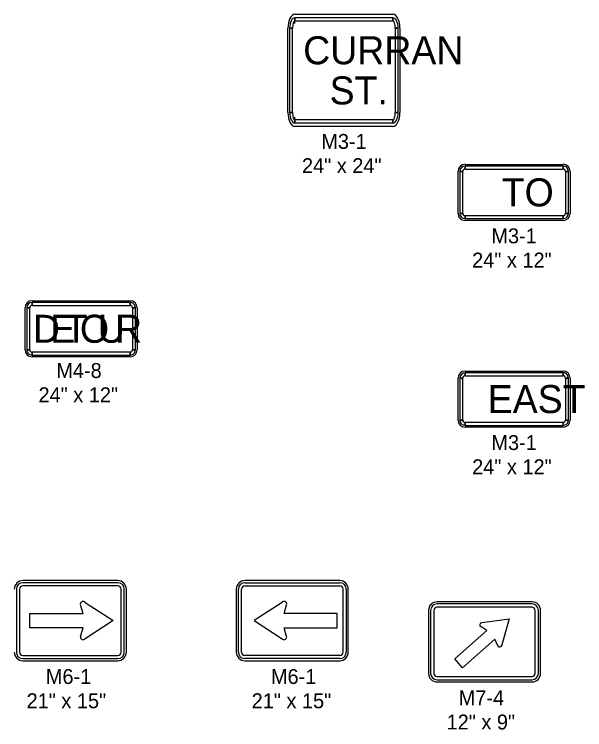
# Model space of a CAD drawing. Extents: x 10133 to 81668, y 6132 to 11018.
# Drawn here: x 10961.7 to 11267.8, y 6734.5 to 7118.2 of the extents above; entities that cross this region are included whole.
import ezdxf

# ---------------------------------------------------------------- set-up
doc = ezdxf.new("R2010")
doc.units = 0
for name, color, linetype in [('dsnTextFinalPlan', 7, 'Continuous'), ('Level 10', 7, 'Continuous'), ('Level 5', 7, 'Continuous')]:
    doc.layers.add(name, color=color, linetype=linetype)

msp = doc.modelspace()

# ---------------------------------------------------------------- linework, layer by layer
at = {"layer": 'dsnTextFinalPlan'}
for p, q in [((11239.58, 6803.08), (11188.62, 6803.08)), ((11184.03, 6798.5), (11184.03, 6764.72)), ((11244.16, 6764.72), (11244.16, 6798.5)), ((11188.62, 6760.13), (11239.58, 6760.13))]:
    msp.add_line(p, q, dxfattribs=at)
for points in [[(11212.88, 6791.95), (11227.25, 6794.02), (11223.39, 6780.04)], [(11221.17, 6779.52), (11219.55, 6783.04), (11202.22, 6767.75), (11198.07, 6772.46), (11215.39, 6787.75), (11212.1, 6789.78)]]:
    msp.add_lwpolyline(points, dxfattribs=at)
for centre, radius, start, end in [((11188.62, 6798.5), 4.58, 90, 180), ((11239.58, 6798.5), 4.58, 360, 90), ((11212.72, 6790.75), 1.16, 98.0346, 237.3927), ((11196.35, 6906.73), 115.96, 278.0346, 278.1951), ((11222.2, 6780.01), 1.14, 205.4546, 344.7341), ((11335.17, 6749.18), 115.96, 164.5667, 164.7341), ((11188.62, 6764.72), 4.58, 180, 270), ((11239.58, 6764.72), 4.58, 270, 0)]:
    msp.add_arc(centre, radius, start, end, dxfattribs=at)
at = {"layer": 'Level 10'}
for p, q in [((11112.34, 7118.21), (11164.95, 7118.21)), ((11112.34, 7113.2), (11112.34, 7116.34)), ((11164.95, 7116.34), (11164.95, 7114.77)), ((11108.58, 7065.6), (11108.58, 7110.7)), ((11109.52, 7110.7), (11111.09, 7110.7)), ((11166.21, 7110.7), (11167.77, 7110.7)), ((11168.71, 7110.7), (11168.71, 7065.6)), ((11111.09, 7065.6), (11109.52, 7065.6)), ((11167.77, 7065.6), (11166.21, 7065.6)), ((11112.34, 7059.97), (11112.34, 7063.1)), ((11164.95, 7061.53), (11164.95, 7059.97)), ((11164.95, 7058.09), (11112.34, 7058.09)), ((11203.64, 7037.74), (11256.26, 7037.74)), ((11199.89, 7011.44), (11199.89, 7033.99)), ((11200.83, 7033.99), (11202.39, 7033.99)), ((11203.64, 7035.24), (11203.64, 7036.8)), ((11256.26, 7036.8), (11256.26, 7035.24)), ((11257.51, 7033.99), (11259.07, 7033.99)), ((11260.01, 7033.99), (11260.01, 7011.44)), ((11202.39, 7011.44), (11200.83, 7011.44)), ((11259.07, 7011.44), (11257.51, 7011.44)), ((11203.64, 7008.62), (11203.64, 7010.19)), ((11256.26, 7007.68), (11203.64, 7007.68)), ((11256.26, 7010.19), (11256.26, 7008.62)), ((10971.27, 6964.58), (11023.89, 6964.58)), ((10967.52, 6938.28), (10967.52, 6960.83)), ((10968.46, 6960.83), (10970.02, 6960.83)), ((10971.27, 6962.08), (10971.27, 6963.65)), ((11023.89, 6963.65), (11023.89, 6962.08)), ((11025.14, 6960.83), (11026.71, 6960.83)), ((11027.65, 6960.83), (11027.65, 6938.28)), ((10970.02, 6938.28), (10968.46, 6938.28)), ((11026.71, 6938.28), (11025.14, 6938.28)), ((10971.27, 6935.46), (10971.27, 6937.03)), ((11023.89, 6934.52), (10971.27, 6934.52)), ((11023.89, 6937.03), (11023.89, 6935.46)), ((11203.64, 6926.87), (11256.26, 6926.87)), ((11203.64, 6924.36), (11203.64, 6925.93)), ((11256.26, 6925.93), (11256.26, 6924.36)), ((11199.89, 6900.56), (11199.89, 6923.11)), ((11200.83, 6923.11), (11202.39, 6923.11)), ((11257.51, 6923.11), (11259.07, 6923.11)), ((11260.01, 6923.11), (11260.01, 6900.56)), ((11202.39, 6900.56), (11200.83, 6900.56)), ((11203.64, 6897.74), (11203.64, 6899.31)), ((11256.26, 6899.31), (11256.26, 6897.74)), ((11259.07, 6900.56), (11257.51, 6900.56)), ((11256.26, 6896.8), (11203.64, 6896.8)), ((11017.29, 6814.47), (10966.33, 6814.47)), ((11017.29, 6813.33), (10966.33, 6813.33)), ((11017.29, 6811.61), (10966.33, 6811.61)), ((11136.42, 6814.47), (11085.45, 6814.47)), ((11085.46, 6813.33), (11136.43, 6813.33)), ((11085.46, 6811.61), (11136.43, 6811.61)), ((10962.89, 6809.89), (10962.89, 6776.11)), ((10964.61, 6809.89), (10964.61, 6776.11)), ((11019.01, 6776.11), (11019.01, 6809.89)), ((11020.73, 6776.11), (11020.73, 6809.89)), ((11021.88, 6776.11), (11021.88, 6809.89)), ((11080.87, 6809.89), (11080.87, 6776.11)), ((11082.02, 6776.11), (11082.02, 6809.89)), ((11083.74, 6776.11), (11083.74, 6809.89)), ((11138.14, 6809.89), (11138.14, 6776.11)), ((11139.86, 6809.89), (11139.86, 6776.11)), ((11141, 6776.11), (11141, 6809.89)), ((11239.58, 6801.94), (11188.62, 6801.94)), ((11239.58, 6800.22), (11188.62, 6800.22)), ((11185.18, 6798.5), (11185.18, 6764.72)), ((11186.9, 6798.5), (11186.9, 6764.72)), ((11241.3, 6764.72), (11241.3, 6798.5)), ((11243.02, 6764.72), (11243.02, 6798.5)), ((10966.33, 6774.39), (11017.29, 6774.39)), ((10966.33, 6772.67), (11017.29, 6772.67)), ((11136.43, 6774.39), (11085.46, 6774.39)), ((11136.43, 6772.67), (11085.46, 6772.67)), ((10966.33, 6771.53), (11017.29, 6771.53)), ((11085.45, 6771.53), (11136.42, 6771.53)), ((11188.62, 6763), (11239.58, 6763)), ((11188.62, 6761.28), (11239.58, 6761.28))]:
    msp.add_line(p, q, dxfattribs=at)
for points in [[(11164.95, 7116.34), (11112.34, 7116.34), (11112.34, 7114.77), (11164.95, 7114.77), (11164.95, 7116.34)], [(11109.52, 7110.7), (11109.52, 7065.6), (11111.09, 7065.6), (11111.09, 7110.7), (11109.52, 7110.7)], [(11167.77, 7065.6), (11167.77, 7110.7), (11166.21, 7110.7), (11166.21, 7065.6), (11167.77, 7065.6)], [(11112.34, 7059.97), (11164.95, 7059.97), (11164.95, 7061.53), (11112.34, 7061.53), (11112.34, 7059.97)], [(11200.83, 7033.99), (11200.83, 7011.44), (11202.39, 7011.44), (11202.39, 7033.99), (11200.83, 7033.99)], [(11256.26, 7036.8), (11203.64, 7036.8), (11203.64, 7035.24), (11256.26, 7035.24), (11256.26, 7036.8)], [(11259.07, 7011.44), (11259.07, 7033.99), (11257.51, 7033.99), (11257.51, 7011.44), (11259.07, 7011.44)], [(11203.64, 7008.62), (11256.26, 7008.62), (11256.26, 7010.19), (11203.64, 7010.19), (11203.64, 7008.62)], [(10968.46, 6960.83), (10968.46, 6938.28), (10970.02, 6938.28), (10970.02, 6960.83), (10968.46, 6960.83)], [(11023.89, 6963.65), (10971.27, 6963.65), (10971.27, 6962.08), (11023.89, 6962.08), (11023.89, 6963.65)], [(11026.71, 6938.28), (11026.71, 6960.83), (11025.14, 6960.83), (11025.14, 6938.28), (11026.71, 6938.28)], [(10971.27, 6935.46), (11023.89, 6935.46), (11023.89, 6937.03), (10971.27, 6937.03), (10971.27, 6935.46)], [(11256.26, 6925.93), (11203.64, 6925.93), (11203.64, 6924.36), (11256.26, 6924.36), (11256.26, 6925.93)], [(11200.83, 6923.11), (11200.83, 6900.56), (11202.39, 6900.56), (11202.39, 6923.11), (11200.83, 6923.11)], [(11259.07, 6900.56), (11259.07, 6923.11), (11257.51, 6923.11), (11257.51, 6900.56), (11259.07, 6900.56)], [(11203.64, 6897.74), (11256.26, 6897.74), (11256.26, 6899.31), (11203.64, 6899.31), (11203.64, 6897.74)]]:
    msp.add_lwpolyline(points, close=True, dxfattribs=at)
for points in [[(10997.26, 6784.54), (10998.63, 6789.12), (10970.1, 6789.12), (10970.1, 6796.88), (10998.63, 6796.88), (10997.23, 6801.45)], [(10999.73, 6802.82), (11014.72, 6793), (10999.73, 6783.21)], [(11105.41, 6802.82), (11090.42, 6793), (11105.41, 6783.21)], [(11107.88, 6784.54), (11106.51, 6789.12), (11135.04, 6789.12), (11135.04, 6796.88), (11106.51, 6796.88), (11107.91, 6801.45)]]:
    msp.add_lwpolyline(points, dxfattribs=at)
for centre, radius, start, end in [((11203.64, 7033.99), 3.76, 90, 180), ((11256.26, 7033.99), 3.76, 0, 90), ((11203.64, 7033.99), 2.82, 90.0002, 179.9998), ((11203.64, 7033.99), 1.25, 90.0002, 179.9998), ((11256.26, 7033.99), 2.82, 0, 90.0002), ((11256.26, 7033.99), 1.25, 0, 90.0002), ((11203.64, 7011.44), 3.76, 180, 270), ((11203.64, 7011.44), 2.82, 179.9998, 270.0001), ((11203.64, 7011.44), 1.25, 179.9998, 270.0001), ((11256.26, 7011.44), 2.82, 270.0001, 0.0003), ((11256.26, 7011.44), 1.25, 270.0001, 0.0003), ((11256.26, 7011.44), 3.76, 270, 359.9911), ((10971.27, 6960.83), 3.76, 90, 180), ((11023.89, 6960.83), 3.76, 0, 90), ((10971.27, 6960.83), 2.82, 90.0002, 179.9998), ((10971.27, 6960.83), 1.25, 90.0002, 179.9998), ((11023.89, 6960.83), 2.82, 0, 90.0002), ((11023.89, 6960.83), 1.25, 0, 90.0002), ((10971.27, 6938.28), 3.76, 180, 270), ((10971.27, 6938.28), 2.82, 179.9998, 270.0001), ((10971.27, 6938.28), 1.25, 179.9998, 270.0001), ((11023.89, 6938.28), 2.82, 270.0001, 0.0003), ((11023.89, 6938.28), 1.25, 270.0001, 0.0003), ((11023.89, 6938.28), 3.76, 270, 359.9911), ((11203.64, 6923.11), 3.76, 90, 180), ((11203.64, 6923.11), 2.82, 90.0002, 179.9998), ((11256.26, 6923.11), 3.76, 0, 90), ((11256.26, 6923.11), 2.82, 0, 90.0002), ((11203.64, 6923.11), 1.25, 90.0002, 179.9998), ((11256.26, 6923.11), 1.25, 0, 90.0002), ((11203.64, 6900.56), 3.76, 180, 270), ((11203.64, 6900.56), 2.82, 179.9998, 270.0001), ((11203.64, 6900.56), 1.25, 179.9998, 270.0001), ((11256.26, 6900.56), 2.82, 270.0001, 0.0003), ((11256.26, 6900.56), 1.25, 270.0001, 0.0003), ((11256.26, 6900.56), 3.76, 270, 359.9911), ((10966.33, 6809.89), 4.58, 90, 180), ((10966.33, 6809.89), 3.44, 90, 180), ((10966.33, 6809.89), 1.72, 90, 180), ((11017.29, 6809.89), 4.58, 360, 90), ((11017.29, 6809.89), 3.44, 0, 90), ((11017.29, 6809.89), 1.72, 0, 90), ((11085.45, 6809.89), 4.58, 90, 180), ((11085.46, 6809.89), 3.44, 90, 180), ((11085.46, 6809.89), 1.72, 90, 180), ((11136.42, 6809.89), 4.58, 360, 90), ((11136.43, 6809.89), 3.44, 0, 90), ((11136.43, 6809.89), 1.72, 0, 90), ((10998.61, 6801.84), 1.43, 56.6109, 195.9691), ((11106.53, 6801.84), 1.43, 344.0309, 123.3891), ((11078.18, 6922.57), 143.16, 236.6109, 236.7714), ((11026.96, 6922.57), 143.16, 303.2286, 303.3891), ((11188.62, 6798.5), 3.44, 90, 180), ((11188.62, 6798.5), 1.72, 90, 180), ((11239.58, 6798.5), 3.44, 0, 90), ((11239.58, 6798.5), 1.72, 0, 90), ((10998.61, 6784.16), 1.4, 164.0309, 303.3104), ((11106.53, 6784.16), 1.4, 236.6896, 15.9691), ((11078, 6663.34), 143.16, 123.143, 123.3104), ((11027.14, 6663.34), 143.16, 56.6896, 56.857), ((10966.33, 6776.11), 4.58, 180, 270), ((10966.33, 6776.11), 3.44, 180, 270), ((10966.33, 6776.11), 1.72, 180, 270), ((11017.29, 6776.11), 4.58, 270, 0), ((11017.29, 6776.11), 3.44, 270, 360), ((11017.29, 6776.11), 1.72, 270, 0), ((11085.45, 6776.11), 4.58, 180, 270), ((11085.46, 6776.11), 3.44, 180, 270), ((11085.46, 6776.11), 1.72, 180, 270), ((11136.42, 6776.11), 4.58, 270, 0), ((11136.43, 6776.11), 3.44, 270, 0), ((11136.43, 6776.11), 1.72, 270, 0), ((11188.62, 6764.72), 3.44, 180, 270), ((11188.62, 6764.72), 1.72, 180, 270), ((11239.58, 6764.72), 3.44, 270, 360), ((11239.58, 6764.72), 1.72, 270, 0)]:
    msp.add_arc(centre, radius, start, end, dxfattribs=at)
for centre, major_axis, ratio, start_param, end_param in [((11112.34, 7110.7), (0, 7.52), 0.5, 6.283185, 7.853982), ((11164.95, 7110.7), (0, 7.52), 0.5, 4.712389, 6.283185), ((11112.34, 7110.7), (0, 5.64), 0.5, 0.000004, 1.570794), ((11112.34, 7110.7), (0, 4.07), 0.307692, 0.000004, 1.570794), ((11164.95, 7110.7), (0, 5.64), 0.5, 4.712389, 6.283189), ((11164.95, 7110.7), (0, 4.07), 0.307692, 4.712389, 6.283189), ((11112.34, 7065.6), (0, 7.52), 0.5, 1.570796, 3.141593), ((11112.34, 7065.6), (0, 5.64), 0.5, 1.570794, 3.141594), ((11112.34, 7065.6), (0, 4.07), 0.307692, 1.570794, 3.141594), ((11164.95, 7065.6), (0, 5.64), 0.5, 3.141594, 4.712394), ((11164.95, 7065.6), (0, 4.07), 0.307692, 3.141594, 4.712394), ((11164.95, 7065.6), (0, 7.52), 0.5, 3.141593, 4.712234)]:
    msp.add_ellipse(centre, major_axis=major_axis, ratio=ratio, start_param=start_param, end_param=end_param, dxfattribs=at)

# ---------------------------------------------------------------- texts
for s, height, p in [('CURRAN', 15.032, (11116.76, 7091.4)), ('ST.', 15.032, (11130.96, 7069.87)), ('TO', 15.032, (11223.31, 7015.2)), ('D', 15.03, (10971.76, 6942.04)), ('E', 15.03, (10981, 6942.04)), ('T', 15.03, (10988.78, 6942.04)), ('O', 15.03, (10996.98, 6942.04)), ('U', 15.03, (11006.58, 6942.04)), ('R', 15.03, (11015.81, 6942.04)), ('EAST', 15.032, (11215.81, 6904.32))]:
    msp.add_text(s, height=height, dxfattribs=at).set_placement(p)
at = {"layer": 'Level 5'}
for s, p in [('M3-1', (11126.47, 7046.04)), ('24" x 24"', (11116.13, 7033.04)), ('M3-1', (11217.77, 6995.39)), ('24" x 12"', (11207.44, 6982.39)), ('M4-8', (10984.28, 6923.13)), ('24" x 12"', (10974.73, 6910.13)), ('M3-1', (11217.77, 6884.51)), ('24" x 12"', (11207.44, 6871.51)), ('M6-1', (10978.68, 6759.02)), ('M6-1', (11099.46, 6759.02)), ('21" x 15"', (10968.34, 6746.02)), ('21" x 15"', (11089.13, 6746.02)), ('M7-4', (11200.21, 6747.62)), ('12" x 9"', (11193.74, 6734.62))]:
    msp.add_text(s, height=8, dxfattribs=at).set_placement(p)

doc.saveas('drawing.dxf')
